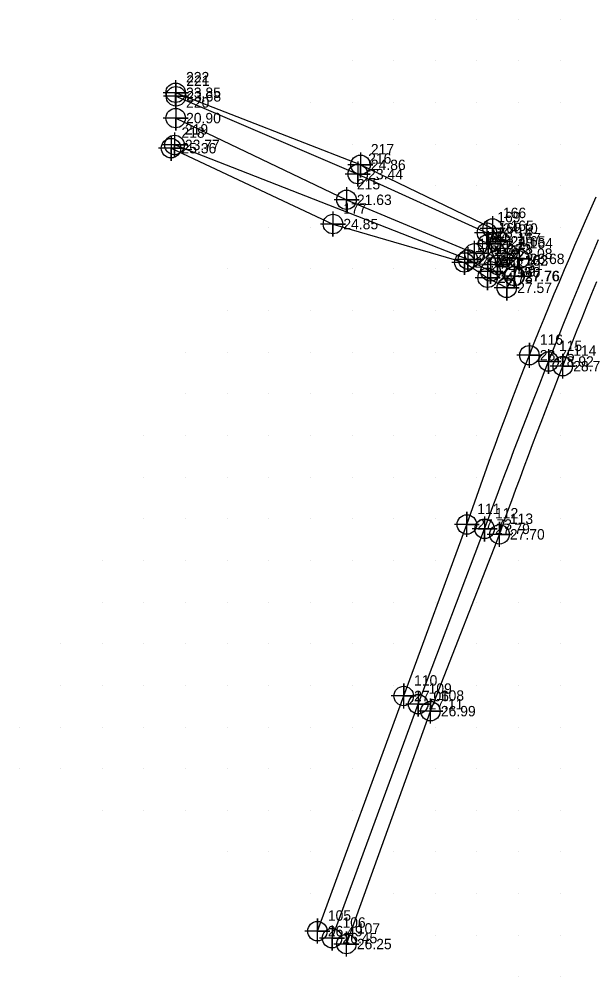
# Model space of a CAD drawing. Extents: x 2204340 to 2204783, y 268170 to 268760.
# Drawn here: x 2204340 to 2204478.1, y 268170 to 268400 of the extents above; entities that cross this region are included whole.
import ezdxf

# ---------------------------------------------------------------- set-up
doc = ezdxf.new("R2010")
doc.units = 0
for name, color, linetype in [('Exist DTM Breakline', 7, 'Continuous'), ('Exist DTM Breakline Cogo Elevation', 7, 'Continuous'), ('Exist DTM Breakline Cogo Number', 7, 'Continuous'), ('Exist DTM Breakline Cogo Point CELL', 7, 'Continuous'), ('Exist DTM Crownline', 7, 'Continuous'), ('Exist DTM Crownline Cogo Elevation', 7, 'Continuous'), ('Exist DTM Crownline Cogo Number', 7, 'Continuous'), ('Exist DTM Crownline Cogo Point CELL', 7, 'Continuous'), ('Exist DTM QL2 LIDAR Elevation Point', 7, 'Continuous'), ('Exist Roads Soil', 7, 'Continuous'), ('Exist Roads Soil Cogo Elevation', 7, 'Continuous'), ('Exist Roads Soil Cogo Number', 7, 'Continuous'), ('Exist Roads Soil Cogo Point CELL', 7, 'Continuous')]:
    doc.layers.add(name, color=color, linetype=linetype)

msp = doc.modelspace()

# ---------------------------------------------------------------- linework, layer by layer
at = {"layer": 'Exist DTM Breakline'}
for points in [[(2204376.51, 268369.01), (2204415.42, 268350.79), (2204447, 268341.57), (2204452.58, 268337.91), (2204457.19, 268335.47), (2204459.08, 268338.31), (2204460.2, 268342.43), (2204457.31, 268343.68), (2204455.59, 268346.63), (2204453.77, 268349.72), (2204422.03, 268365.01), (2204377.61, 268382.32)], [(2204377.68, 268381.47), (2204421.38, 268362.79), (2204452.41, 268348.72), (2204452.71, 268346.06), (2204454.98, 268340.98), (2204453.28, 268339.43), (2204447.87, 268342.28), (2204377.34, 268369.79)], [(2204377.62, 268376.24), (2204418.68, 268356.62), (2204449.39, 268343.76)]]:
    msp.add_lwpolyline(points, dxfattribs=at)
at = {"layer": 'Exist DTM Breakline Cogo Point CELL'}
for points in [[(2204377.61, 268385.32), (2204377.61, 268379.32), (2204377.61, 268382.32), (2204380.61, 268382.32), (2204374.61, 268382.32)], [(2204377.68, 268384.47), (2204377.68, 268378.47), (2204377.68, 268381.47), (2204380.68, 268381.47), (2204374.68, 268381.47)], [(2204377.62, 268379.24), (2204377.62, 268373.24), (2204377.62, 268376.24), (2204380.62, 268376.24), (2204374.62, 268376.24)], [(2204376.51, 268372.01), (2204376.51, 268366.01), (2204376.51, 268369.01), (2204379.51, 268369.01), (2204373.51, 268369.01)], [(2204377.34, 268372.79), (2204377.34, 268366.79), (2204377.34, 268369.79), (2204380.34, 268369.79), (2204374.34, 268369.79)], [(2204422.03, 268368.01), (2204422.03, 268362.01), (2204422.03, 268365.01), (2204425.03, 268365.01), (2204419.03, 268365.01)], [(2204421.38, 268365.79), (2204421.38, 268359.79), (2204421.38, 268362.79), (2204424.38, 268362.79), (2204418.38, 268362.79)], [(2204418.68, 268359.62), (2204418.68, 268353.62), (2204418.68, 268356.62), (2204421.68, 268356.62), (2204415.68, 268356.62)], [(2204415.42, 268353.79), (2204415.42, 268347.79), (2204415.42, 268350.79), (2204418.42, 268350.79), (2204412.42, 268350.79)], [(2204453.77, 268352.72), (2204453.77, 268346.72), (2204453.77, 268349.72), (2204456.77, 268349.72), (2204450.77, 268349.72)], [(2204452.41, 268351.72), (2204452.41, 268345.72), (2204452.41, 268348.72), (2204455.41, 268348.72), (2204449.41, 268348.72)], [(2204452.71, 268349.06), (2204452.71, 268343.06), (2204452.71, 268346.06), (2204455.71, 268346.06), (2204449.71, 268346.06)], [(2204455.59, 268349.63), (2204455.59, 268343.63), (2204455.59, 268346.63), (2204458.59, 268346.63), (2204452.59, 268346.63)], [(2204449.39, 268346.76), (2204449.39, 268340.76), (2204449.39, 268343.76), (2204452.39, 268343.76), (2204446.39, 268343.76)], [(2204457.31, 268346.68), (2204457.31, 268340.68), (2204457.31, 268343.68), (2204460.31, 268343.68), (2204454.31, 268343.68)], [(2204447, 268344.57), (2204447, 268338.57), (2204447, 268341.57), (2204450, 268341.57), (2204444, 268341.57)], [(2204447.87, 268345.28), (2204447.87, 268339.28), (2204447.87, 268342.28), (2204450.87, 268342.28), (2204444.87, 268342.28)], [(2204454.98, 268343.98), (2204454.98, 268337.98), (2204454.98, 268340.98), (2204457.98, 268340.98), (2204451.98, 268340.98)], [(2204460.2, 268345.43), (2204460.2, 268339.43), (2204460.2, 268342.43), (2204463.2, 268342.43), (2204457.2, 268342.43)], [(2204453.28, 268342.43), (2204453.28, 268336.43), (2204453.28, 268339.43), (2204456.28, 268339.43), (2204450.28, 268339.43)], [(2204458.97, 268341.3), (2204458.97, 268335.3), (2204458.97, 268338.3), (2204461.97, 268338.3), (2204455.97, 268338.3)], [(2204459.08, 268341.31), (2204459.08, 268335.31), (2204459.08, 268338.31), (2204462.08, 268338.31), (2204456.08, 268338.31)], [(2204452.58, 268340.91), (2204452.58, 268334.91), (2204452.58, 268337.91), (2204455.58, 268337.91), (2204449.58, 268337.91)], [(2204457.19, 268338.47), (2204457.19, 268332.47), (2204457.19, 268335.47), (2204460.19, 268335.47), (2204454.19, 268335.47)]]:
    msp.add_lwpolyline(points, dxfattribs=at)
for centre in [(2204377.61, 268382.32), (2204377.68, 268381.47), (2204377.62, 268376.24), (2204376.51, 268369.01), (2204377.34, 268369.79), (2204422.03, 268365.01), (2204421.38, 268362.79), (2204418.68, 268356.62), (2204415.42, 268350.79), (2204452.41, 268348.72), (2204453.77, 268349.72), (2204452.71, 268346.06), (2204455.59, 268346.63), (2204449.39, 268343.76), (2204457.31, 268343.68), (2204447, 268341.57), (2204447.87, 268342.28), (2204454.98, 268340.98), (2204460.2, 268342.43), (2204453.28, 268339.43), (2204452.58, 268337.91), (2204458.97, 268338.3), (2204459.08, 268338.31), (2204457.19, 268335.47)]:
    msp.add_circle(centre, 2.34, dxfattribs=at)
at = {"layer": 'Exist DTM Crownline'}
msp.add_lwpolyline([(2204415.2, 268179.3), (2204435.9, 268235.49), (2204451.87, 268277.59), (2204452.86, 268280.28), (2204453.86, 268282.97), (2204454.86, 268285.66), (2204455.86, 268288.35), (2204456.87, 268291.03), (2204457.89, 268293.72), (2204458.91, 268296.4), (2204459.93, 268299.08), (2204460.96, 268301.75), (2204462, 268304.43), (2204463.04, 268307.1), (2204464.08, 268309.78), (2204465.13, 268312.45), (2204466.18, 268315.11), (2204467.24, 268317.78), (2204468.41, 268320.72), (2204469.59, 268323.67), (2204470.77, 268326.6), (2204471.96, 268329.54), (2204473.16, 268332.48), (2204474.36, 268335.41), (2204475.57, 268338.34), (2204476.78, 268341.27), (2204478, 268344.19), (2204479.23, 268347.11)], dxfattribs=at)
at = {"layer": 'Exist DTM Crownline Cogo Point CELL'}
for points in [[(2204467.24, 268320.78), (2204467.24, 268314.78), (2204467.24, 268317.78), (2204470.24, 268317.78), (2204464.24, 268317.78)], [(2204451.87, 268280.59), (2204451.87, 268274.59), (2204451.87, 268277.59), (2204454.87, 268277.59), (2204448.87, 268277.59)], [(2204435.9, 268238.49), (2204435.9, 268232.49), (2204435.9, 268235.49), (2204438.9, 268235.49), (2204432.9, 268235.49)], [(2204415.2, 268182.3), (2204415.2, 268176.3), (2204415.2, 268179.3), (2204418.2, 268179.3), (2204412.2, 268179.3)]]:
    msp.add_lwpolyline(points, dxfattribs=at)
for centre in [(2204467.24, 268317.78), (2204451.87, 268277.59), (2204435.9, 268235.49), (2204415.2, 268179.3)]:
    msp.add_circle(centre, 2.34, dxfattribs=at)
at = {"layer": 'Exist DTM QL2 LIDAR Elevation Point'}
for p, q in [((2204420, 268400), (2204420, 268400)), ((2204430, 268400), (2204430, 268400)), ((2204440, 268400), (2204440, 268400)), ((2204450, 268400), (2204450, 268400)), ((2204460, 268400), (2204460, 268400)), ((2204470, 268400), (2204470, 268400)), ((2204420, 268390), (2204420, 268390)), ((2204430, 268390), (2204430, 268390)), ((2204440, 268390), (2204440, 268390)), ((2204450, 268390), (2204450, 268390)), ((2204460, 268390), (2204460, 268390)), ((2204470, 268390), (2204470, 268390)), ((2204410, 268380), (2204410, 268380)), ((2204420, 268380), (2204420, 268380)), ((2204430, 268380), (2204430, 268380)), ((2204440, 268380), (2204440, 268380)), ((2204450, 268380), (2204450, 268380)), ((2204460, 268380), (2204460, 268380)), ((2204470, 268380), (2204470, 268380)), ((2204420, 268370), (2204420, 268370)), ((2204430, 268370), (2204430, 268370)), ((2204440, 268370), (2204440, 268370)), ((2204450, 268370), (2204450, 268370)), ((2204460, 268370), (2204460, 268370)), ((2204470, 268370), (2204470, 268370)), ((2204440, 268360), (2204440, 268360)), ((2204450, 268360), (2204450, 268360)), ((2204460, 268360), (2204460, 268360)), ((2204470, 268360), (2204470, 268360)), ((2204400, 268350), (2204400, 268350)), ((2204410, 268350), (2204410, 268350)), ((2204460, 268350), (2204460, 268350)), ((2204470, 268350), (2204470, 268350)), ((2204390, 268340), (2204390, 268340)), ((2204400, 268340), (2204400, 268340)), ((2204410, 268340), (2204410, 268340)), ((2204420, 268340), (2204420, 268340)), ((2204430, 268340), (2204430, 268340)), ((2204440, 268340), (2204440, 268340)), ((2204470, 268340), (2204470, 268340)), ((2204390, 268330), (2204390, 268330)), ((2204400, 268330), (2204400, 268330)), ((2204410, 268330), (2204410, 268330)), ((2204420, 268330), (2204420, 268330)), ((2204430, 268330), (2204430, 268330)), ((2204440, 268330), (2204440, 268330)), ((2204450, 268330), (2204450, 268330)), ((2204460, 268330), (2204460, 268330)), ((2204380, 268320), (2204380, 268320)), ((2204390, 268320), (2204390, 268320)), ((2204400, 268320), (2204400, 268320)), ((2204410, 268320), (2204410, 268320)), ((2204420, 268320), (2204420, 268320)), ((2204430, 268320), (2204430, 268320)), ((2204440, 268320), (2204440, 268320)), ((2204450, 268320), (2204450, 268320)), ((2204460, 268320), (2204460, 268320)), ((2204380, 268310), (2204380, 268310)), ((2204390, 268310), (2204390, 268310)), ((2204400, 268310), (2204400, 268310)), ((2204410, 268310), (2204410, 268310)), ((2204420, 268310), (2204420, 268310)), ((2204430, 268310), (2204430, 268310)), ((2204440, 268310), (2204440, 268310)), ((2204450, 268310), (2204450, 268310)), ((2204470, 268310), (2204470, 268310)), ((2204370, 268300), (2204370, 268300)), ((2204380, 268300), (2204380, 268300)), ((2204390, 268300), (2204390, 268300)), ((2204400, 268300), (2204400, 268300)), ((2204410, 268300), (2204410, 268300)), ((2204420, 268300), (2204420, 268300)), ((2204430, 268300), (2204430, 268300)), ((2204440, 268300), (2204440, 268300)), ((2204450, 268300), (2204450, 268300)), ((2204470, 268300), (2204470, 268300)), ((2204370, 268290), (2204370, 268290)), ((2204380, 268290), (2204380, 268290)), ((2204390, 268290), (2204390, 268290)), ((2204400, 268290), (2204400, 268290)), ((2204410, 268290), (2204410, 268290)), ((2204420, 268290), (2204420, 268290)), ((2204430, 268290), (2204430, 268290)), ((2204440, 268290), (2204440, 268290)), ((2204450, 268290), (2204450, 268290)), ((2204470, 268290), (2204470, 268290)), ((2204370, 268280), (2204370, 268280)), ((2204380, 268280), (2204380, 268280)), ((2204390, 268280), (2204390, 268280)), ((2204400, 268280), (2204400, 268280)), ((2204410, 268280), (2204410, 268280)), ((2204420, 268280), (2204420, 268280)), ((2204430, 268280), (2204430, 268280)), ((2204440, 268280), (2204440, 268280)), ((2204460, 268280), (2204460, 268280)), ((2204470, 268280), (2204470, 268280)), ((2204360, 268270), (2204360, 268270)), ((2204370, 268270), (2204370, 268270)), ((2204380, 268270), (2204380, 268270)), ((2204390, 268270), (2204390, 268270)), ((2204400, 268270), (2204400, 268270)), ((2204410, 268270), (2204410, 268270)), ((2204420, 268270), (2204420, 268270)), ((2204430, 268270), (2204430, 268270)), ((2204440, 268270), (2204440, 268270)), ((2204460, 268270), (2204460, 268270)), ((2204470, 268270), (2204470, 268270)), ((2204360, 268260), (2204360, 268260)), ((2204370, 268260), (2204370, 268260)), ((2204380, 268260), (2204380, 268260)), ((2204390, 268260), (2204390, 268260)), ((2204400, 268260), (2204400, 268260)), ((2204410, 268260), (2204410, 268260)), ((2204420, 268260), (2204420, 268260)), ((2204430, 268260), (2204430, 268260)), ((2204440, 268260), (2204440, 268260)), ((2204450, 268260), (2204450, 268260)), ((2204460, 268260), (2204460, 268260)), ((2204470, 268260), (2204470, 268260)), ((2204350, 268250), (2204350, 268250)), ((2204360, 268250), (2204360, 268250)), ((2204370, 268250), (2204370, 268250)), ((2204380, 268250), (2204380, 268250)), ((2204390, 268250), (2204390, 268250)), ((2204400, 268250), (2204400, 268250)), ((2204410, 268250), (2204410, 268250)), ((2204420, 268250), (2204420, 268250)), ((2204430, 268250), (2204430, 268250)), ((2204450, 268250), (2204450, 268250)), ((2204460, 268250), (2204460, 268250)), ((2204470, 268250), (2204470, 268250)), ((2204350, 268240), (2204350, 268240)), ((2204360, 268240), (2204360, 268240)), ((2204370, 268240), (2204370, 268240)), ((2204380, 268240), (2204380, 268240)), ((2204390, 268240), (2204390, 268240)), ((2204400, 268240), (2204400, 268240)), ((2204410, 268240), (2204410, 268240)), ((2204420, 268240), (2204420, 268240)), ((2204430, 268240), (2204430, 268240)), ((2204450, 268240), (2204450, 268240)), ((2204460, 268240), (2204460, 268240)), ((2204470, 268240), (2204470, 268240)), ((2204340, 268230), (2204340, 268230)), ((2204350, 268230), (2204350, 268230)), ((2204360, 268230), (2204360, 268230)), ((2204370, 268230), (2204370, 268230)), ((2204380, 268230), (2204380, 268230)), ((2204390, 268230), (2204390, 268230)), ((2204400, 268230), (2204400, 268230)), ((2204410, 268230), (2204410, 268230)), ((2204420, 268230), (2204420, 268230)), ((2204440, 268230), (2204440, 268230)), ((2204450, 268230), (2204450, 268230)), ((2204460, 268230), (2204460, 268230)), ((2204470, 268230), (2204470, 268230)), ((2204340, 268220), (2204340, 268220)), ((2204350, 268220), (2204350, 268220)), ((2204360, 268220), (2204360, 268220)), ((2204370, 268220), (2204370, 268220)), ((2204380, 268220), (2204380, 268220)), ((2204390, 268220), (2204390, 268220)), ((2204400, 268220), (2204400, 268220)), ((2204410, 268220), (2204410, 268220)), ((2204420, 268220), (2204420, 268220)), ((2204440, 268220), (2204440, 268220)), ((2204450, 268220), (2204450, 268220)), ((2204460, 268220), (2204460, 268220)), ((2204470, 268220), (2204470, 268220)), ((2204360, 268210), (2204360, 268210)), ((2204370, 268210), (2204370, 268210)), ((2204380, 268210), (2204380, 268210)), ((2204390, 268210), (2204390, 268210)), ((2204400, 268210), (2204400, 268210)), ((2204410, 268210), (2204410, 268210)), ((2204420, 268210), (2204420, 268210)), ((2204440, 268210), (2204440, 268210)), ((2204450, 268210), (2204450, 268210)), ((2204460, 268210), (2204460, 268210)), ((2204470, 268210), (2204470, 268210)), ((2204390, 268200), (2204390, 268200)), ((2204400, 268200), (2204400, 268200)), ((2204410, 268200), (2204410, 268200)), ((2204430, 268200), (2204430, 268200)), ((2204440, 268200), (2204440, 268200)), ((2204450, 268200), (2204450, 268200)), ((2204460, 268200), (2204460, 268200)), ((2204470, 268200), (2204470, 268200)), ((2204410, 268190), (2204410, 268190)), ((2204430, 268190), (2204430, 268190)), ((2204440, 268190), (2204440, 268190)), ((2204450, 268190), (2204450, 268190)), ((2204460, 268190), (2204460, 268190)), ((2204470, 268190), (2204470, 268190)), ((2204440, 268180), (2204440, 268180)), ((2204450, 268180), (2204450, 268180)), ((2204460, 268180), (2204460, 268180)), ((2204470, 268180), (2204470, 268180)), ((2204460, 268170), (2204460, 268170)), ((2204470, 268170), (2204470, 268170))]:
    msp.add_line(p, q, dxfattribs=at)
at = {"layer": 'Exist Roads Soil'}
for points in [[(2204411.69, 268180.98), (2204432.42, 268237.45), (2204447.59, 268278.65), (2204448.54, 268281.38), (2204449.49, 268284.1), (2204450.45, 268286.83), (2204451.42, 268289.55), (2204452.4, 268292.27), (2204453.38, 268294.99), (2204454.38, 268297.7), (2204455.38, 268300.41), (2204456.39, 268303.11), (2204457.41, 268305.82), (2204458.44, 268308.52), (2204459.48, 268311.22), (2204460.52, 268313.91), (2204461.57, 268316.6), (2204462.63, 268319.29), (2204463.81, 268322.24), (2204465, 268325.19), (2204466.19, 268328.13), (2204467.4, 268331.07), (2204468.61, 268334), (2204469.84, 268336.93), (2204471.07, 268339.86), (2204472.32, 268342.78), (2204473.57, 268345.7), (2204474.84, 268348.62), (2204476.11, 268351.53), (2204477.4, 268354.43), (2204478.69, 268357.33)], [(2204418.66, 268177.88), (2204438.85, 268233.81), (2204455.45, 268276.27), (2204456.42, 268278.98), (2204457.4, 268281.68), (2204458.39, 268284.39), (2204459.38, 268287.09), (2204460.37, 268289.79), (2204461.38, 268292.48), (2204462.38, 268295.18), (2204463.4, 268297.87), (2204464.42, 268300.56), (2204465.44, 268303.25), (2204466.47, 268305.94), (2204467.51, 268308.62), (2204468.55, 268311.3), (2204469.59, 268313.98), (2204470.65, 268316.66), (2204471.8, 268319.57), (2204472.95, 268322.48), (2204474.12, 268325.38), (2204475.29, 268328.29), (2204476.46, 268331.19), (2204477.65, 268334.08), (2204478.83, 268336.98)]]:
    msp.add_lwpolyline(points, dxfattribs=at)
at = {"layer": 'Exist Roads Soil Cogo Point CELL'}
for points in [[(2204462.63, 268316.29), (2204462.63, 268322.29), (2204462.63, 268319.29), (2204465.63, 268319.29), (2204459.63, 268319.29)], [(2204470.65, 268313.66), (2204470.65, 268319.66), (2204470.65, 268316.66), (2204473.65, 268316.66), (2204467.65, 268316.66)], [(2204447.59, 268275.64), (2204447.59, 268281.64), (2204447.59, 268278.64), (2204450.59, 268278.64), (2204444.59, 268278.64)], [(2204455.44, 268273.27), (2204455.44, 268279.27), (2204455.44, 268276.27), (2204458.44, 268276.27), (2204452.44, 268276.27)], [(2204432.42, 268234.45), (2204432.42, 268240.45), (2204432.42, 268237.45), (2204435.42, 268237.45), (2204429.42, 268237.45)], [(2204438.85, 268230.81), (2204438.85, 268236.81), (2204438.85, 268233.81), (2204441.85, 268233.81), (2204435.85, 268233.81)], [(2204411.69, 268177.98), (2204411.69, 268183.98), (2204411.69, 268180.98), (2204414.69, 268180.98), (2204408.69, 268180.98)], [(2204418.66, 268174.88), (2204418.66, 268180.88), (2204418.66, 268177.88), (2204421.66, 268177.88), (2204415.66, 268177.88)]]:
    msp.add_lwpolyline(points, dxfattribs=at)
for centre in [(2204462.63, 268319.29), (2204470.65, 268316.66), (2204447.59, 268278.64), (2204455.44, 268276.27), (2204432.42, 268237.45), (2204438.85, 268233.81), (2204411.69, 268180.98), (2204418.66, 268177.88)]:
    msp.add_circle(centre, 2.34, dxfattribs=at)

# ---------------------------------------------------------------- texts
at = {"layer": 'Exist DTM Breakline Cogo Elevation'}
for s, p in [('23.85', (2204380.11, 268381.07)), ('23.68', (2204380.18, 268380.22)), ('20.90', (2204380.12, 268374.99)), ('23.77', (2204379.84, 268368.54)), ('25.36', (2204379.01, 268367.76)), ('23.44', (2204423.88, 268361.54)), ('24.86', (2204424.53, 268363.76)), ('21.63', (2204421.18, 268355.37)), ('24.85', (2204417.92, 268349.54)), ('24.10', (2204456.27, 268348.47)), ('23.14', (2204454.91, 268347.47)), ('24.65', (2204458.09, 268345.38)), ('23.20', (2204455.21, 268344.81)), ('22.85', (2204450.37, 268341.03)), ('22.72', (2204451.89, 268342.51)), ('23.08', (2204459.81, 268342.43)), ('26.68', (2204462.7, 268341.18)), ('24.03', (2204449.5, 268340.32)), ('23.31', (2204457.48, 268339.73)), ('24.73', (2204455.08, 268336.66)), ('23.29', (2204455.78, 268338.18)), ('27.76', (2204461.47, 268337.05)), ('27.76', (2204461.58, 268337.06)), ('27.57', (2204459.69, 268334.22))]:
    msp.add_text(s, height=2.5, dxfattribs=at).set_placement(p)
at = {"layer": 'Exist DTM Breakline Cogo Number'}
for s, p in [('222', (2204380.11, 268384.82)), ('221', (2204380.18, 268383.97)), ('220', (2204380.12, 268378.74)), ('218', (2204379.01, 268371.51)), ('219', (2204379.84, 268372.29)), ('217', (2204424.53, 268367.51)), ('216', (2204423.88, 268365.29)), ('215', (2204421.18, 268359.12)), ('177', (2204417.92, 268353.29)), ('169', (2204454.91, 268351.22)), ('166', (2204456.27, 268352.22)), ('168', (2204455.21, 268348.56)), ('165', (2204458.09, 268349.13)), ('174', (2204451.89, 268346.26)), ('167', (2204459.81, 268346.18)), ('176', (2204449.5, 268344.07)), ('175', (2204450.37, 268344.78)), ('173', (2204457.48, 268343.48)), ('164', (2204462.7, 268344.93)), ('172', (2204455.78, 268341.93)), ('162', (2204461.47, 268340.8)), ('163', (2204461.58, 268340.81)), ('171', (2204455.08, 268340.41)), ('170', (2204459.69, 268337.97))]:
    msp.add_text(s, height=2.5, dxfattribs=at).set_placement(p)
at = {"layer": 'Exist DTM Crownline Cogo Elevation'}
for s, p in [('28.92', (2204469.74, 268316.53)), ('27.79', (2204454.37, 268276.34)), ('27.11', (2204438.4, 268234.24)), ('26.45', (2204417.7, 268178.05))]:
    msp.add_text(s, height=2.5, dxfattribs=at).set_placement(p)
at = {"layer": 'Exist DTM Crownline Cogo Number'}
for s, p in [('115', (2204469.74, 268320.28)), ('112', (2204454.37, 268280.09)), ('109', (2204438.4, 268237.99)), ('106', (2204417.7, 268181.8))]:
    msp.add_text(s, height=2.5, dxfattribs=at).set_placement(p)
at = {"layer": 'Exist Roads Soil Cogo Elevation'}
for s, p in [('28.75', (2204465.13, 268318.04)), ('28.78', (2204473.15, 268315.41)), ('27.73', (2204450.09, 268277.39)), ('27.70', (2204457.94, 268275.02)), ('27.06', (2204434.92, 268236.2)), ('26.99', (2204441.35, 268232.56)), ('26.49', (2204414.19, 268179.73)), ('26.25', (2204421.16, 268176.63))]:
    msp.add_text(s, height=2.5, dxfattribs=at).set_placement(p)
at = {"layer": 'Exist Roads Soil Cogo Number'}
for s, p in [('116', (2204465.13, 268321.79)), ('114', (2204473.15, 268319.16)), ('111', (2204450.09, 268281.14)), ('113', (2204457.94, 268278.77)), ('110', (2204434.92, 268239.95)), ('108', (2204441.35, 268236.31)), ('105', (2204414.19, 268183.48)), ('107', (2204421.16, 268180.38))]:
    msp.add_text(s, height=2.5, dxfattribs=at).set_placement(p)

doc.saveas('drawing.dxf')
